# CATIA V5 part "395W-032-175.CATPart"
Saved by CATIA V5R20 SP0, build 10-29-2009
Part number: 395W-032-175
Bounding box of the stored display mesh (mm): x -10 to 165, y -20.01 to 20, z -20 to 20
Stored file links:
  C:\Users\Raffaele\Desktop\3D X SITO CF\PERNI -STAFFE SOLLEVAMENTO\395W\395W-032-175.CATPart
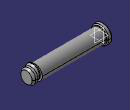
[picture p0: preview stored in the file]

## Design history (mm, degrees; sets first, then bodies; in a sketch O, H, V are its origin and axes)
Body1 (main body)
  Solid1 "ImportedBody": solid without history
